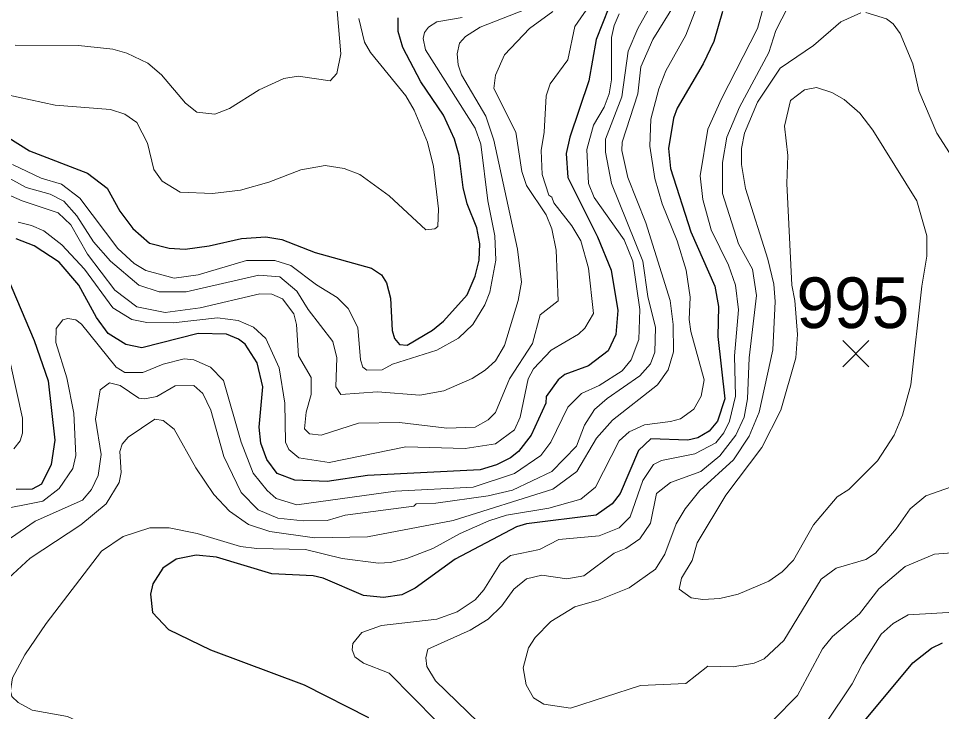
# Model space of a CAD drawing. Extents: x 265 to 291.4, y 7731.5 to 7759.6.
# Drawn here: x 281.619 to 283.077, y 7754.605 to 7755.701 of the extents above; entities that cross this region are included whole.
import ezdxf
from ezdxf.enums import TextEntityAlignment as Align

# ---------------------------------------------------------------- set-up
doc = ezdxf.new("R2010")
doc.units = 0
doc.header["$LTSCALE"] = 0.032
for name, color, linetype, lineweight in [('1', 7, 'Continuous', 25), ('2', 7, 'Continuous', 13), ('21', 7, 'Continuous', 25), ('61', 7, 'Continuous', 13)]:
    doc.layers.add(name, color=color, linetype=linetype, lineweight=lineweight)

msp = doc.modelspace()

# ---------------------------------------------------------------- linework, layer by layer
at = {"layer": '1'}
for points in [[(282.5618, 7755.7435), (282.5316, 7755.6671), (282.5204, 7755.6019), (282.4902, 7755.5128), (282.4846, 7755.4874), (282.487, 7755.4492), (282.5339, 7755.3553), (282.5554, 7755.3028), (282.5658, 7755.2392), (282.5626, 7755.201), (282.5506, 7755.1755), (282.5196, 7755.1516), (282.4823, 7755.1381), (282.4719, 7755.1294), (282.4528, 7755.1031)], [(282.7312, 7755.7117), (282.7177, 7755.664), (282.701, 7755.629), (282.6596, 7755.559), (282.6541, 7755.5431), (282.6461, 7755.4953), (282.6493, 7755.4635), (282.6811, 7755.3633), (282.7193, 7755.2774), (282.7249, 7755.2455), (282.7241, 7755.1978), (282.7352, 7755.0992), (282.7233, 7755.0642), (282.7105, 7755.0482), (282.6923, 7755.0379), (282.6764, 7755.0339), (282.6183, 7755.0363), (282.5984, 7755.018), (282.5697, 7754.9496), (282.557, 7754.9337), (282.5316, 7754.9154), (282.4218, 7754.9019), (282.4059, 7754.8971), (282.3088, 7754.8462), (282.246, 7754.8), (282.2245, 7754.7897), (282.1959, 7754.7857), (282.1641, 7754.7889), (282.1004, 7754.816), (282.0845, 7754.8199), (282.0193, 7754.8231), (281.9318, 7754.8494), (281.9, 7754.8525), (281.8681, 7754.8462), (281.8474, 7754.8319), (281.8315, 7754.8072), (281.8276, 7754.7905), (281.8307, 7754.7619), (281.8562, 7754.7348), (281.9222, 7754.703), (282.0702, 7754.6473), (282.172, 7754.5956)], [(281.534, 7755.5558), (281.6366, 7755.4913), (281.7281, 7755.4563), (281.7591, 7755.4325), (281.779, 7755.3959), (281.7997, 7755.3688), (281.826, 7755.3457), (281.857, 7755.3378), (281.8825, 7755.3362), (281.9206, 7755.341), (281.9716, 7755.3529), (282.0097, 7755.3553), (282.0352, 7755.3513), (282.0877, 7755.3306), (282.1768, 7755.306), (282.1927, 7755.2956), (282.2006, 7755.2829), (282.207, 7755.2583), (282.2094, 7755.2074), (282.2134, 7755.1946), (282.2213, 7755.1851), (282.2333, 7755.1843), (282.273, 7755.2081), (282.2905, 7755.2224), (282.3279, 7755.2638), (282.3406, 7755.2933), (282.347, 7755.3187), (282.3478, 7755.3442), (282.343, 7755.3696), (282.3279, 7755.4078), (282.3215, 7755.4333), (282.3152, 7755.4842), (282.308, 7755.5096), (282.2905, 7755.5478), (282.2547, 7755.6003), (282.2261, 7755.6544), (282.2189, 7755.6799), (282.2189, 7755.7013)], [(282.3486, 7754.987), (282.1704, 7754.9782), (282.1068, 7754.9687), (282.0559, 7754.9711), (282.028, 7754.9814), (282.0113, 7755.0037), (282.0018, 7755.0292), (281.9994, 7755.0546), (282.0049, 7755.1183), (281.9962, 7755.1564), (281.9771, 7755.1858), (281.9668, 7755.1938), (281.9477, 7755.2018), (281.9031, 7755.2026), (281.8141, 7755.1803), (281.7886, 7755.1851), (281.7607, 7755.2026), (281.7424, 7755.228), (281.7146, 7755.2789), (281.6836, 7755.3155), (281.6438, 7755.341), (281.6152, 7755.3521)], [(281.5873, 7755.3235), (281.6438, 7755.1914), (281.6661, 7755.1278), (281.6764, 7755.0339), (281.6708, 7754.9958), (281.6557, 7754.9647), (281.6406, 7754.9568), (281.6152, 7754.956)], [(282.4528, 7755.1031), (282.452, 7755.0928), (282.4289, 7755.0419), (282.4091, 7755.0164), (282.3963, 7755.0061), (282.3741, 7754.9949), (282.3486, 7754.987)], [(282.76, 7754.4529), (282.7872, 7754.4616), (282.845, 7754.4888), (282.8815, 7754.5154), (282.9433, 7754.5752), (283.0319, 7754.6823), (283.0614, 7754.7054), (283.0789, 7754.7141)]]:
    msp.add_lwpolyline(points, dxfattribs=at)
at = {"layer": '2'}
for points in [[(282.1283, 7755.6449), (282.1187, 7755.7562)], [(282.2794, 7754.5901), (282.2049, 7754.6658), (282.1641, 7754.6815), (282.1505, 7754.6919), (282.1465, 7754.703), (282.1473, 7754.7126), (282.1617, 7754.7301), (282.1927, 7754.7412), (282.2802, 7754.7515), (282.312, 7754.7627), (282.3407, 7754.7818), (282.3542, 7754.7977), (282.3804, 7754.8398), (282.3963, 7754.8518), (282.4425, 7754.8613), (282.4727, 7754.8772), (282.5364, 7754.8828), (282.5682, 7754.8955), (282.5857, 7754.913), (282.6055, 7754.9703), (282.6222, 7754.9958), (282.635, 7755.0021), (282.6875, 7755.0124), (282.7209, 7755.0299), (282.7336, 7755.0459), (282.7424, 7755.0642), (282.7519, 7755.1039), (282.7503, 7755.1676), (282.7567, 7755.24), (282.7519, 7755.2789), (282.7408, 7755.3108), (282.7137, 7755.3665), (282.7002, 7755.4142), (282.6962, 7755.4516), (282.7082, 7755.5255), (282.7296, 7755.5733), (282.7869, 7755.6846), (282.8044, 7755.7499)], [(282.6358, 7755.7538), (282.5976, 7755.6846), (282.5825, 7755.6488), (282.5721, 7755.5765), (282.5467, 7755.5096), (282.5467, 7755.489), (282.5562, 7755.4396)], [(282.8434, 7755.7363), (282.8156, 7755.6815), (282.8044, 7755.6465), (282.7583, 7755.5606), (282.7384, 7755.5128), (282.7312, 7755.473), (282.7312, 7755.4237), (282.7567, 7755.3442), (282.779, 7755.3044), (282.7853, 7755.263), (282.7734, 7755.1644), (282.771, 7755.0992), (282.7654, 7755.0705), (282.7527, 7755.0419), (282.7273, 7755.0093), (282.697, 7754.9846), (282.6493, 7754.9671), (282.627, 7754.9496), (282.6175, 7754.9027), (282.6008, 7754.878), (282.5785, 7754.8629), (282.5602, 7754.8557), (282.5125, 7754.8199), (282.4854, 7754.8152), (282.4457, 7754.8207), (282.4218, 7754.8152), (282.4019, 7754.7985), (282.3828, 7754.7722), (282.3613, 7754.7515), (282.3327, 7754.734), (282.2659, 7754.7038), (282.2627, 7754.6903), (282.2643, 7754.6767), (282.2778, 7754.6537), (282.3454, 7754.5885)], [(282.4282, 7755.718), (282.3486, 7755.687), (282.3255, 7755.6719), (282.316, 7755.6616), (282.312, 7755.6449), (282.3136, 7755.6274), (282.3192, 7755.6115), (282.3574, 7755.5462), (282.3701, 7755.508), (282.4075, 7755.3362), (282.4138, 7755.2837), (282.4083, 7755.2551), (282.3868, 7755.1835), (282.3725, 7755.1596), (282.3566, 7755.1445), (282.3359, 7755.1318), (282.2913, 7755.1119), (282.2532, 7755.1055), (282.1863, 7755.1103), (282.1283, 7755.1063), (282.1203, 7755.1183), (282.1219, 7755.1644), (282.1155, 7755.1899), (282.0766, 7755.2408), (282.059, 7755.2694), (282.032, 7755.2925), (281.9986, 7755.2949), (281.8841, 7755.2686), (281.8411, 7755.2686), (281.8093, 7755.2789), (281.7647, 7755.3171), (281.7377, 7755.3474), (281.7114, 7755.3887), (281.6907, 7755.4118), (281.6693, 7755.4229), (281.6311, 7755.4333), (281.5937, 7755.4539)], [(282.5252, 7755.7276), (282.4982, 7755.6878), (282.487, 7755.6353), (282.4592, 7755.5971), (282.4528, 7755.5781), (282.4496, 7755.5208), (282.4449, 7755.4921), (282.4465, 7755.454), (282.4568, 7755.4213), (282.4616, 7755.4182), (282.4647, 7755.4094), (282.4934, 7755.3728), (282.5077, 7755.349), (282.5196, 7755.306), (282.5276, 7755.2344), (282.5141, 7755.2113), (282.5037, 7755.2018), (282.4608, 7755.1763), (282.4329, 7755.1469), (282.4242, 7755.131), (282.4115, 7755.0705), (282.4027, 7755.0506), (282.3725, 7755.0284), (282.3248, 7755.0212), (282.2309, 7755.0236), (282.11, 7754.9989), (282.0622, 7755.0061), (282.0463, 7755.0196), (282.0408, 7755.0308), (282.04, 7755.0928), (282.0312, 7755.1485), (282.0097, 7755.1946), (281.9906, 7755.2129), (281.966, 7755.2233), (281.9334, 7755.2272), (281.8634, 7755.2193), (281.822, 7755.2201), (281.7981, 7755.2248), (281.7679, 7755.2431), (281.7234, 7755.3044), (281.6876, 7755.3426), (281.6589, 7755.3648), (281.6398, 7755.3736), (281.6184, 7755.3784)], [(281.6293, 7754.6949), (281.6629, 7754.7444), (281.7504, 7754.8589), (281.7846, 7754.882), (281.8268, 7754.8955), (281.857, 7754.8955), (281.9016, 7754.8868), (281.97, 7754.8661), (281.9954, 7754.8629), (282.0726, 7754.8613), (282.1307, 7754.847), (282.1879, 7754.8398), (282.207, 7754.8406), (282.2325, 7754.847), (282.2738, 7754.8629), (282.3168, 7754.8868), (282.3621, 7754.9067), (282.39, 7754.9154), (282.4568, 7754.9265), (282.5077, 7754.9409), (282.5308, 7754.96), (282.5682, 7755.0331), (282.5841, 7755.0474), (282.6079, 7755.0586), (282.6493, 7755.0634), (282.6652, 7755.0681), (282.6859, 7755.0832), (282.6978, 7755.1039), (282.7026, 7755.1294), (282.6811, 7755.2058), (282.6787, 7755.2249), (282.6803, 7755.2599), (282.674, 7755.3028), (282.6596, 7755.349), (282.6358, 7755.4078), (282.6246, 7755.4476), (282.6167, 7755.4985), (282.6183, 7755.5415), (282.631, 7755.5892), (282.6421, 7755.6178), (282.6732, 7755.6743), (282.6907, 7755.7188)], [(281.7576, 7754.9337), (281.7782, 7754.9671), (281.7814, 7754.983), (281.779, 7755.0164), (281.783, 7755.0276), (281.7926, 7755.0387), (281.8347, 7755.0673), (281.8475, 7755.065), (281.865, 7755.0514), (281.8992, 7754.9902), (281.9278, 7754.948), (281.9525, 7754.9218), (281.9827, 7754.9011), (282.0161, 7754.8899), (282.0869, 7754.8796), (282.1704, 7754.8812), (282.3057, 7754.9074), (282.4632, 7754.9568), (282.5013, 7754.9846), (282.5324, 7755.0371), (282.5578, 7755.0658), (282.6286, 7755.1214), (282.6453, 7755.1453), (282.6541, 7755.1739), (282.6533, 7755.2169), (282.6485, 7755.2551), (282.6103, 7755.3776), (282.5817, 7755.4492), (282.5721, 7755.4921), (282.5729, 7755.5049), (282.5976, 7755.5812), (282.6024, 7755.6242), (282.6215, 7755.6671), (282.6565, 7755.7244)], [(281.5643, 7755.4388), (281.6247, 7755.4126), (281.682, 7755.3935), (281.7019, 7755.3744), (281.7281, 7755.3283), (281.7711, 7755.271), (281.8061, 7755.2447), (281.8506, 7755.236), (281.9063, 7755.2431), (282.0002, 7755.2654), (282.0193, 7755.2646), (282.036, 7755.2575), (282.0543, 7755.2336), (282.0583, 7755.2169), (282.0614, 7755.1676), (282.0813, 7755.1334), (282.0813, 7755.1063), (282.0734, 7755.0785), (282.071, 7755.0522), (282.0789, 7755.0443), (282.0972, 7755.0419), (282.1561, 7755.061), (282.2213, 7755.0618), (282.2961, 7755.053), (282.3407, 7755.0546), (282.3613, 7755.0665), (282.3725, 7755.0777), (282.3947, 7755.131), (282.4313, 7755.1867), (282.4433, 7755.232), (282.4719, 7755.2543), (282.4687, 7755.3346), (282.4616, 7755.368), (282.4528, 7755.3903), (282.4218, 7755.4365), (282.4146, 7755.4587), (282.4051, 7755.5208), (282.3701, 7755.59), (282.3725, 7755.6107), (282.3868, 7755.6433), (282.4266, 7755.6846), (282.4632, 7755.7117)], [(281.6096, 7755.4699), (281.655, 7755.4484), (281.6868, 7755.4388), (281.7162, 7755.4166), (281.7759, 7755.337), (281.8021, 7755.3132), (281.8204, 7755.302), (281.865, 7755.2901), (281.9031, 7755.2956), (281.9795, 7755.3179), (282.0241, 7755.3179), (282.0495, 7755.31), (282.0901, 7755.2797), (282.1227, 7755.2598), (282.1402, 7755.2424), (282.1553, 7755.2121), (282.1593, 7755.1612), (282.1633, 7755.1493), (282.1696, 7755.1445), (282.1935, 7755.1453), (282.2102, 7755.154), (282.2802, 7755.1763), (282.3144, 7755.1954), (282.3367, 7755.2169), (282.3558, 7755.2479), (282.3637, 7755.2678), (282.3733, 7755.3187), (282.3717, 7755.3569), (282.3605, 7755.4126), (282.3494, 7755.5017), (282.3406, 7755.5271), (282.2619, 7755.6512), (282.2587, 7755.6687), (282.2603, 7755.6783), (282.2667, 7755.687), (282.2802, 7755.695), (282.32, 7755.7021)], [(282.95, 7755.7093), (282.9182, 7755.695), (282.8752, 7755.6576), (282.8227, 7755.6218), (282.7869, 7755.5685), (282.7662, 7755.5192), (282.7615, 7755.4953), (282.7615, 7755.4699), (282.7678, 7755.4317), (282.8028, 7755.3203), (282.8124, 7755.2805), (282.8148, 7755.2535), (282.8108, 7755.1771), (282.7893, 7755.0785), (282.7734, 7755.0403), (282.7487, 7755.0029), (282.6955, 7754.9544), (282.6724, 7754.9258), (282.6581, 7754.9019), (282.6405, 7754.8542), (282.6254, 7754.8303), (282.5841, 7754.8008), (282.5364, 7754.7818), (282.4982, 7754.7706), (282.46, 7754.7475), (282.4353, 7754.7221), (282.425, 7754.7062), (282.4162, 7754.6744), (282.421, 7754.6473), (282.4329, 7754.6267), (282.4489, 7754.6171), (282.491, 7754.6107), (282.6016, 7754.6465), (282.6732, 7754.6497), (282.7082, 7754.6768), (282.748, 7754.6759), (282.7814, 7754.6815), (282.7973, 7754.6887), (282.8281, 7754.7175), (282.8871, 7754.8144), (282.911, 7754.8319), (282.958, 7754.8454), (282.9731, 7754.8557), (283.0057, 7754.8939), (283.0279, 7754.9258), (283.0526, 7754.9464), (283.1234, 7754.9711)], [(282.5196, 7755.4396), (282.5172, 7755.4937), (282.5276, 7755.5319), (282.5443, 7755.5606), (282.5522, 7755.5812), (282.5562, 7755.6035), (282.5562, 7755.6703), (282.5602, 7755.6894), (282.5682, 7755.7077)], [(283.1091, 7755.4587), (283.0701, 7755.5192), (283.0415, 7755.586), (283.0319, 7755.629), (283.012, 7755.6767), (283.0009, 7755.6918), (282.9906, 7755.6997), (282.958, 7755.7101)], [(282.1569, 7755.7006), (282.1656, 7755.6631), (282.1752, 7755.6465), (282.2309, 7755.5781), (282.2444, 7755.5558), (282.2651, 7755.5049), (282.2746, 7755.4667), (282.2826, 7755.3999), (282.2818, 7755.372), (282.277, 7755.368), (282.2627, 7755.3664), (282.2046, 7755.4205), (282.1585, 7755.4539), (282.1338, 7755.4635), (282.1036, 7755.4683), (282.0654, 7755.4611), (282.0145, 7755.442), (281.97, 7755.4293)], [(281.6136, 7755.6584), (281.7138, 7755.6576), (281.7679, 7755.652), (281.7902, 7755.6457), (281.8236, 7755.6297), (281.8451, 7755.6114), (281.8832, 7755.5669), (281.9007, 7755.5526), (281.9294, 7755.5494), (281.9525, 7755.5582)], [(281.9525, 7755.5582), (281.9994, 7755.5876), (282.0384, 7755.6059), (282.0607, 7755.6091), (282.1116, 7755.6019), (282.1219, 7755.6138), (282.1283, 7755.6449)], [(281.8061, 7755.5359), (281.787, 7755.5494), (281.7647, 7755.5566), (281.6772, 7755.5637), (281.5993, 7755.5804)], [(281.97, 7755.4293), (281.9254, 7755.4237), (281.8745, 7755.4261), (281.8459, 7755.4436), (281.8331, 7755.4619), (281.8228, 7755.5033), (281.8061, 7755.5359)], [(282.5562, 7755.4396), (282.6055, 7755.3171), (282.6135, 7755.2614), (282.6254, 7755.2121), (282.6246, 7755.1731), (282.6175, 7755.1549), (282.6008, 7755.1358), (282.5491, 7755.0999), (282.5292, 7755.0825), (282.5133, 7755.0578), (282.5005, 7755.0244), (282.4616, 7754.9846), (282.3995, 7754.9552), (282.3613, 7754.9464), (282.2786, 7754.9345), (282.2476, 7754.9337), (282.2436, 7754.9297), (282.1354, 7754.9154), (282.1068, 7754.9074), (282.0686, 7754.9066), (282.0288, 7754.9106), (281.9978, 7754.9242), (281.9708, 7754.9512), (281.9437, 7755.0085), (281.923, 7755.0817), (281.9103, 7755.1079), (281.896, 7755.1206), (281.8666, 7755.1198), (281.8379, 7755.1031), (281.8188, 7755.0992), (281.8093, 7755.1007), (281.7798, 7755.1206), (281.7631, 7755.1246), (281.748, 7755.1135), (281.7409, 7755.0674), (281.7496, 7755.0117), (281.7448, 7754.9783), (281.7345, 7754.956), (281.7202, 7754.9393), (281.6454, 7754.9059), (281.5913, 7754.8685)], [(282.5872, 7755.1612), (282.5992, 7755.193), (282.6008, 7755.2408), (282.5896, 7755.3171), (282.5761, 7755.3505), (282.5284, 7755.4174), (282.5196, 7755.4396)], [(281.5802, 7754.9226), (281.6573, 7754.9377), (281.6836, 7754.9576), (281.7051, 7754.9894), (281.7098, 7755.0101), (281.7067, 7755.0769), (281.6955, 7755.1326), (281.678, 7755.1883), (281.6788, 7755.2105), (281.6892, 7755.2241), (281.6971, 7755.2264), (281.7098, 7755.2241), (281.7186, 7755.2177), (281.7735, 7755.1493), (281.787, 7755.1413), (281.8156, 7755.1413), (281.8475, 7755.154), (281.8809, 7755.1628), (281.896, 7755.1612), (281.9222, 7755.1493), (281.9429, 7755.1286), (281.9708, 7755.0308), (281.9899, 7754.9822), (282.0121, 7754.9544), (282.0264, 7754.9417), (282.0591, 7754.9321), (282.215, 7754.9536), (282.3375, 7754.9599), (282.4027, 7754.9814), (282.4441, 7755.0101), (282.46, 7755.0308), (282.487, 7755.0864), (282.5085, 7755.1079), (282.5364, 7755.1206), (282.5729, 7755.1437), (282.5872, 7755.1612)], [(281.6064, 7755.1549), (281.6255, 7755.0689), (281.6255, 7755.0451), (281.6215, 7755.0331), (281.612, 7755.0204)], [(281.5507, 7754.6728), (281.5674, 7754.7444), (281.5873, 7754.7921), (281.6032, 7754.816), (281.6374, 7754.8478), (281.7178, 7754.9003), (281.7576, 7754.9337)], [(282.8116, 7754.5916), (282.8498, 7754.6306), (282.8895, 7754.7046), (282.9054, 7754.7237), (282.9476, 7754.7595), (282.9786, 7754.7993), (283.02, 7754.8343), (283.0661, 7754.8541), (283.1823, 7754.8629)], [(283.1155, 7754.7635), (283.0248, 7754.7579), (283.0009, 7754.7444), (282.9818, 7754.7277), (282.9524, 7754.6807), (282.9365, 7754.6489), (282.8935, 7754.5853)], [(282.1728, 7754.5216), (282.1497, 7754.5336), (282.0813, 7754.5495), (282.0225, 7754.5686), (281.9668, 7754.5678), (281.8777, 7754.5447), (281.8284, 7754.5447), (281.7902, 7754.5542), (281.6963, 7754.5972), (281.6406, 7754.6076), (281.6184, 7754.6195), (281.6088, 7754.629), (281.6064, 7754.6378), (281.6096, 7754.6585), (281.6293, 7754.6949)]]:
    msp.add_lwpolyline(points, dxfattribs=at)
msp.add_lwpolyline([(282.8046, 7754.8111), (282.8259, 7754.8263), (282.8434, 7754.8446), (282.8752, 7754.9003), (282.9126, 7754.9448), (282.9309, 7754.956), (282.9763, 7755.0013), (283.0025, 7755.0419), (283.016, 7755.0737), (283.0287, 7755.1214), (283.0462, 7755.2774), (283.0542, 7755.3251), (283.0542, 7755.3569), (283.0383, 7755.4126), (282.9691, 7755.524), (282.9484, 7755.551), (282.9238, 7755.5725), (282.9039, 7755.5836), (282.88, 7755.5916), (282.8609, 7755.5876), (282.8386, 7755.5709), (282.8291, 7755.5303), (282.8346, 7755.4842), (282.8331, 7755.4396), (282.841, 7755.2789), (282.8458, 7755.2551), (282.8498, 7755.201), (282.8474, 7755.1644), (282.8235, 7755.0817), (282.7933, 7755.0228), (282.7368, 7754.9472), (282.6915, 7754.8717), (282.6835, 7754.8438), (282.6668, 7754.816), (282.6628, 7754.7985), (282.6819, 7754.7849), (282.7002, 7754.7825), (282.7273, 7754.7841), (282.7559, 7754.7905)], close=True, dxfattribs=at)
at = {"layer": '21'}
for p, q in [((282.9213, 7755.1914), (282.9625, 7755.1502)), ((282.9625, 7755.1914), (282.9213, 7755.1502))]:
    msp.add_line(p, q, dxfattribs=at)

# ---------------------------------------------------------------- texts
at = {"layer": '61'}
msp.add_text('995', height=0.08, dxfattribs=at).set_placement((282.9373, 7755.2113), align=Align.CENTER)

doc.saveas('drawing.dxf')
